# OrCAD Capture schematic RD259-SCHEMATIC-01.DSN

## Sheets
1 2: size A3
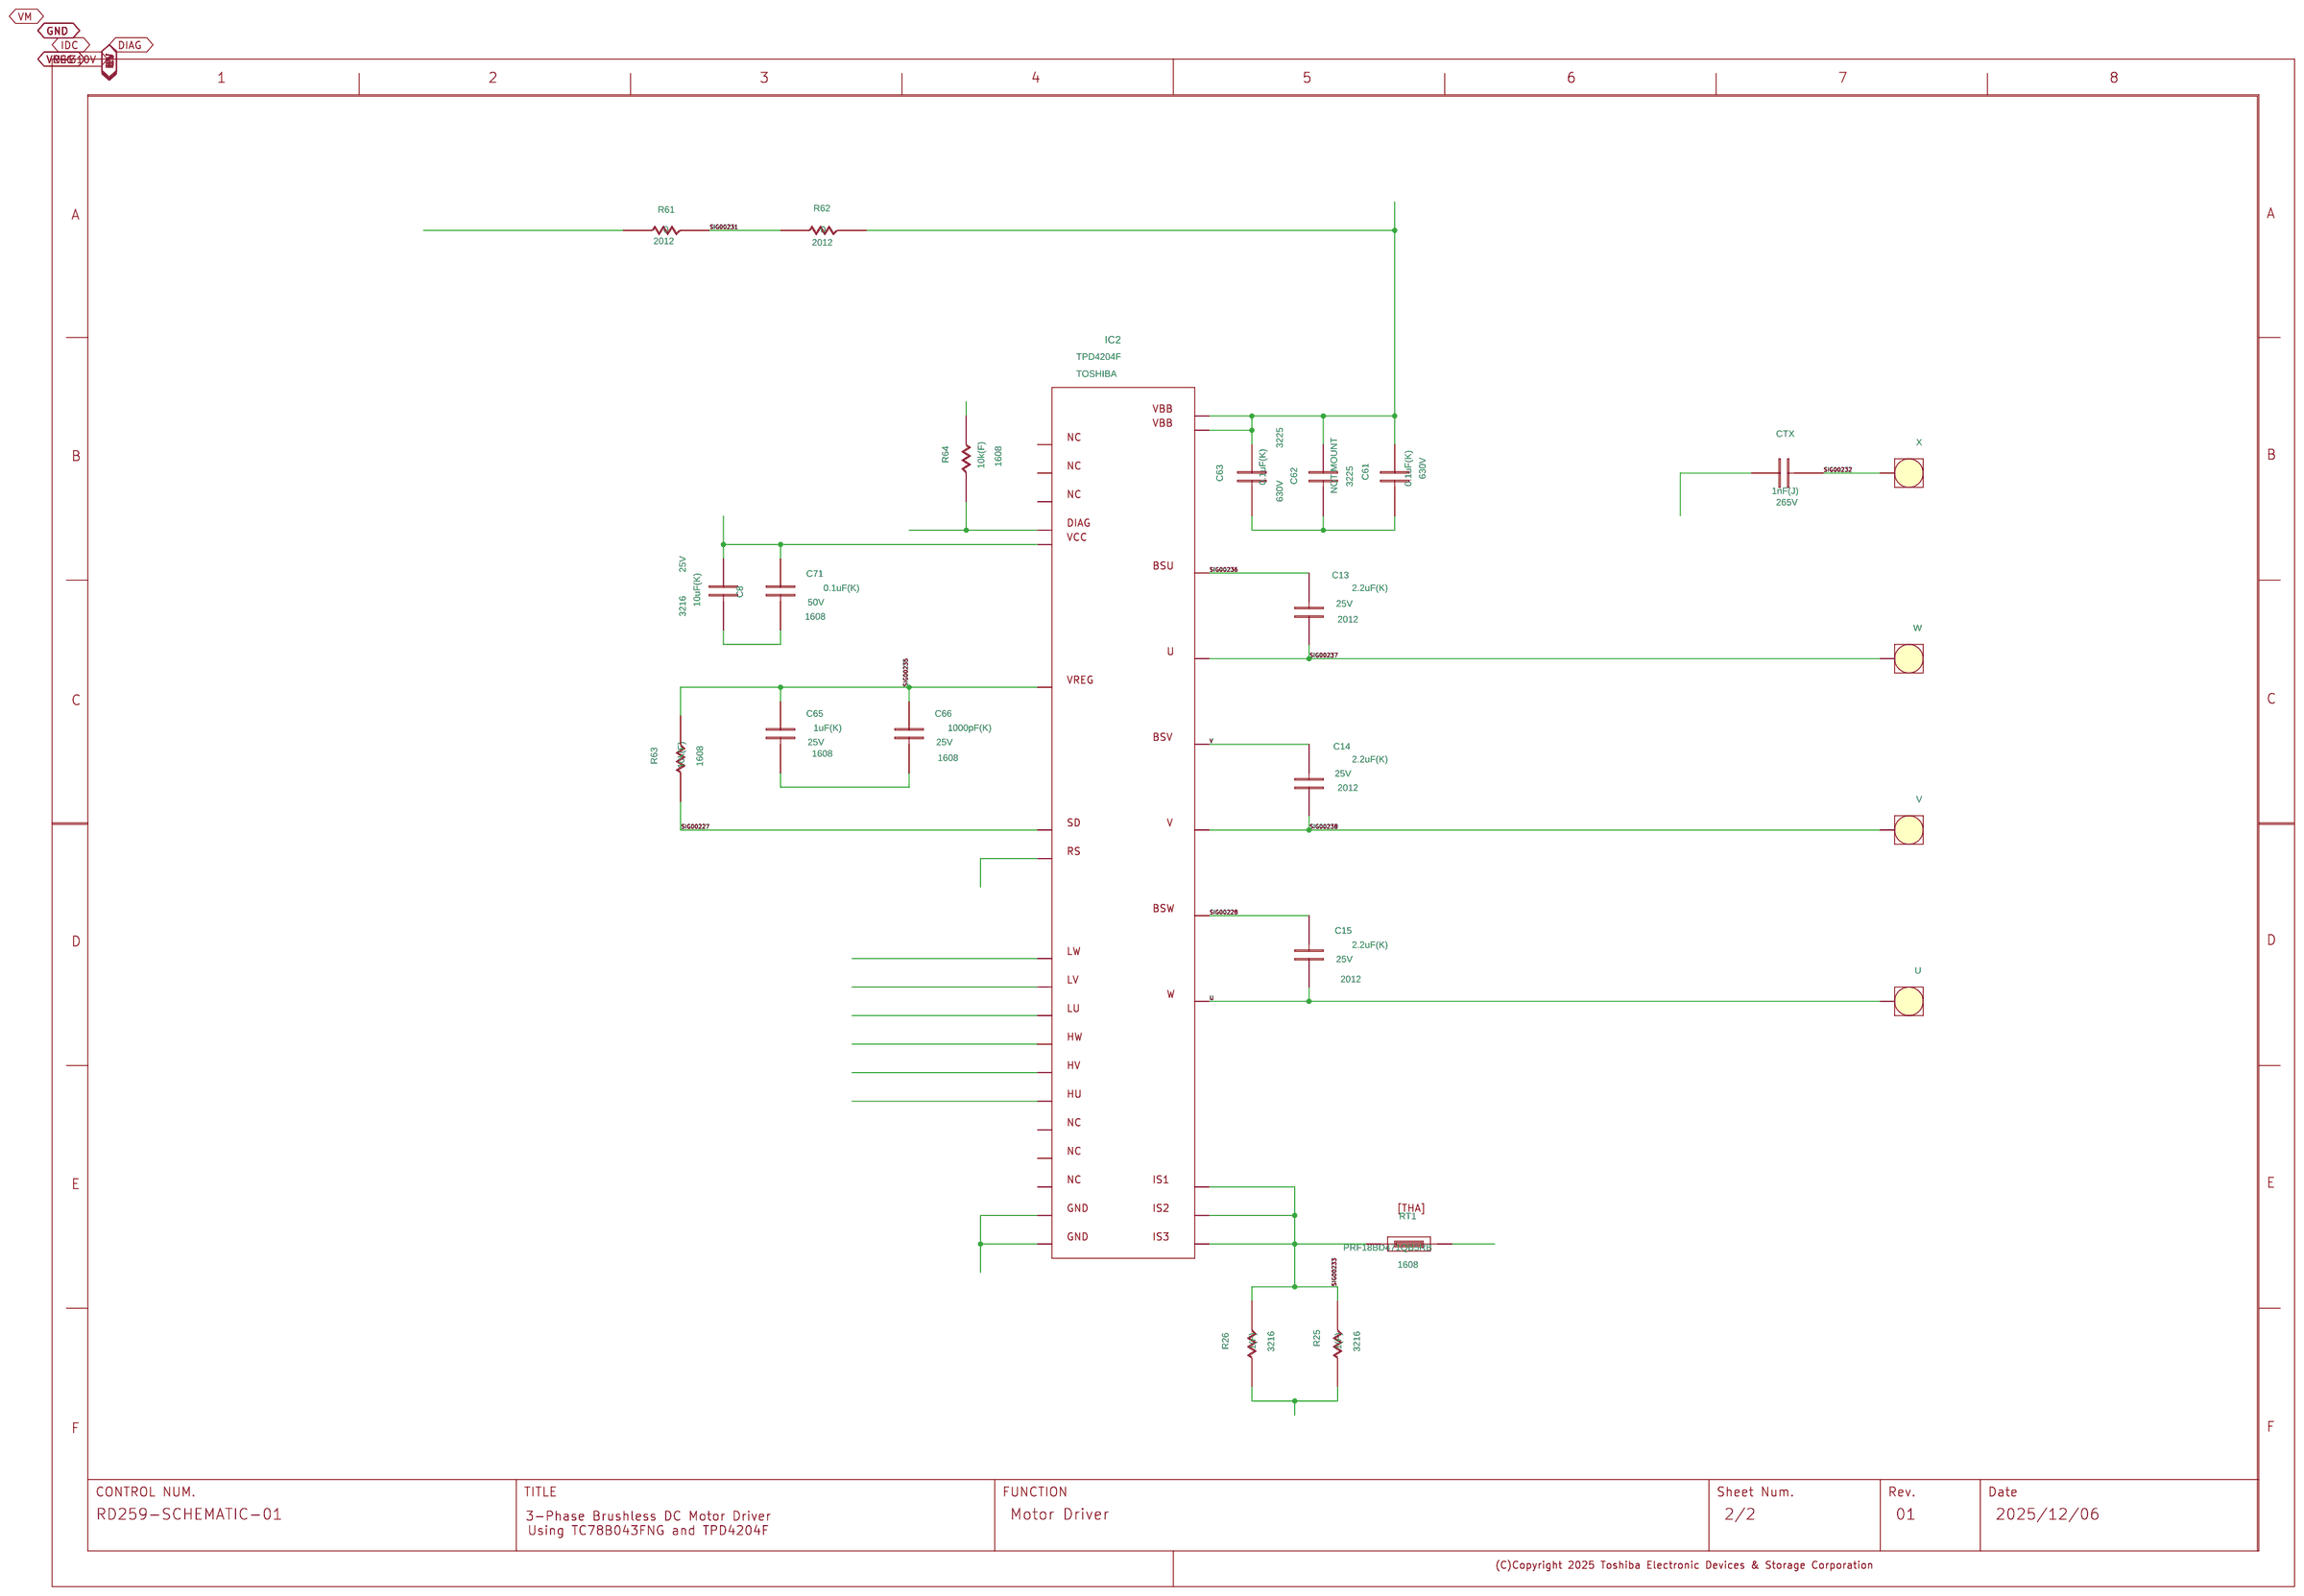
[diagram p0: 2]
2 1: size A3
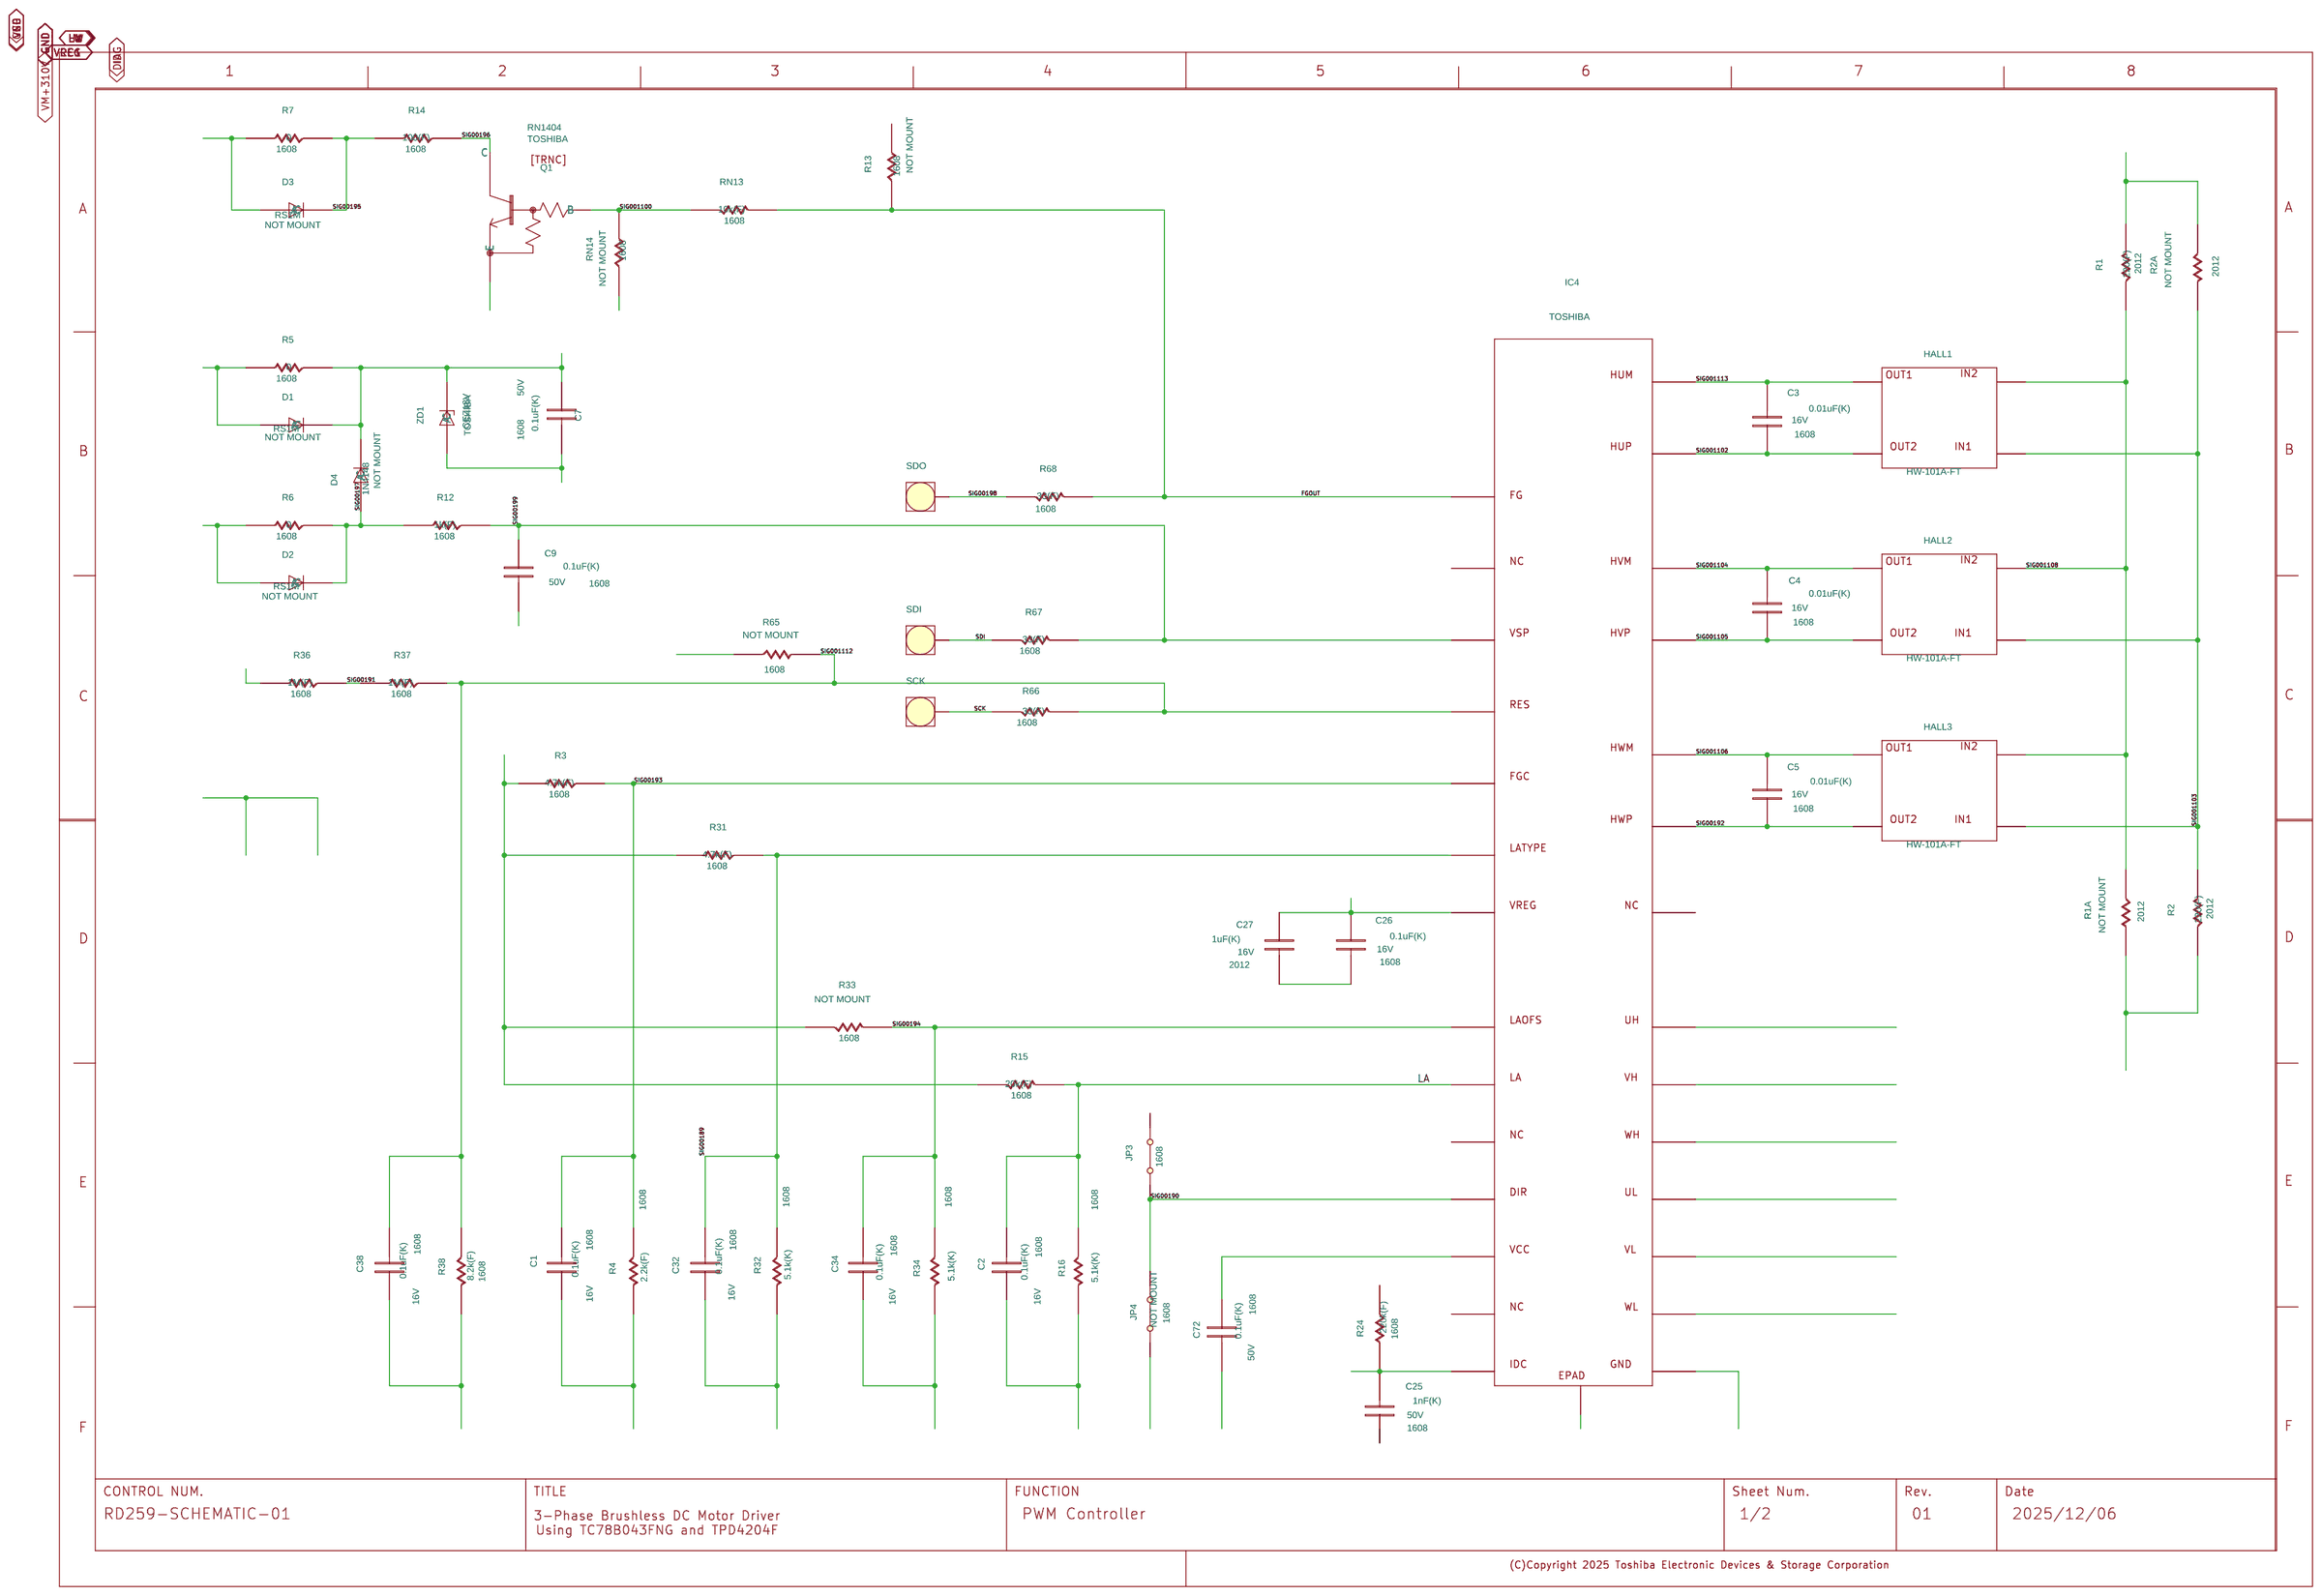
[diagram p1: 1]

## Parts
sheet 1
C1  C
C2  C
C3  C
C4  C
C5  C
C7  C
C9  C
C25  C
C26  C
C27  C
C32  C
C34  C
C38  C
C72  C
D1  D
D2  D
D3  D
D4  D
HALL1  HW-101A-FT
HALL2  HW-101A-FT
HALL3  HW-101A-FT
IC4  TC78B043FNG
JP3  JP
JP4  JP
Q1  TRNC
R1  R
R1A  R
R2  R
R2A  R
R3  R
R4  R
R5  R
R6  R
R7  R
R12  R
R13  R
R14  R
R15  R
R16  R
R24  R
R31  R
R32  R
R33  R
R34  R
R36  R
R37  R
R38  R
R65  R
R66  R
R67  R
R68  R
RN13  R
RN14  R
SCK  PAD_FOR_BLDCS50
SDI  PAD_FOR_BLDCS50
SDO  PAD_FOR_BLDCS50
U?#1  WAKU_DEF100
ZD1  ZD
sheet 2
C8  C
C13  C
C14  C
C15  C
C61  C
C62  C
C63  C
C65  C
C66  C
C71  C
CTX  C
IC2  TPD4204F
R25  R
R26  R
R61  R
R62  R
R63  R
R64  R
RT1  THA
U  PAD_FOR_BLDCS50
U?#2  WAKU_DEF100
V  PAD_FOR_BLDCS50
W  PAD_FOR_BLDCS50
X  PAD_FOR_BLDCS50

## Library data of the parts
C1 C2 C26 C32 C34 C38 = C: COMPONENTTYPE: 4; SAVECOUNT: 0; SIZECODESMD: 1608; VAL1: 0.1uF(K); VAL2: 16V
C3-C5 = C: COMPONENTTYPE: 4; SAVECOUNT: 0; SIZECODESMD: 1608; VAL1: 0.01uF(K); VAL2: 16V
C7 C9 C71 C72 = C: COMPONENTTYPE: 4; SAVECOUNT: 0; SIZECODESMD: 1608; VAL1: 0.1uF(K); VAL2: 50V
C25 = C: COMPONENTTYPE: 4; SAVECOUNT: 0; SIZECODESMD: 1608; VAL1: 1nF(K); VAL2: 50V
C27 = C: COMPONENTTYPE: 4; SAVECOUNT: 0; SIZECODESMD: 2012; VAL1: 1uF(K); VAL2: 16V
D1-D3 = D: COMPONENTTYPE: 4; NOTMNT: NOT MOUNT; VAL3: RS1M
D4 = D: COMPONENTTYPE: 4; NOTMNT: NOT MOUNT; VAL3: 1N4148
HALL1-HALL3 = HW-101A-FT: COMPONENTTYPE: 4
IC4 = TC78B043FNG: COMPONENTTYPE: 4; USERCOMPTEXT3: TOSHIBA
JP3 = JP: COMPONENTTYPE: 4; SAVECOUNT: 0; SIZECODESMD: 1608
JP4 = JP: COMPONENTTYPE: 4; NOTMNT: NOT MOUNT; SAVECOUNT: 0; SIZECODESMD: 1608
Q1 = TRNC: COMPONENTTYPE: 4; DEVICE: RN1404; SAVECOUNT: 0; USERCOMPTEXT3: TOSHIBA; VAL3: RN1404
R1 R2 = R: COMPONENTTYPE: 4; SAVECOUNT: 0; SIZECODESMD: 2012; VAL1: 220(F); VAL2: 100mW
R1A R2A = R: COMPONENTTYPE: 4; NOTMNT: NOT MOUNT; SAVECOUNT: 0; SIZECODESMD: 2012
R3 R31 = R: COMPONENTTYPE: 4; SAVECOUNT: 0; SIZECODESMD: 1608; VAL1: 4.7k(F); VAL2: 100mW
R4 = R: COMPONENTTYPE: 4; SAVECOUNT: 0; SIZECODESMD: 1608; VAL1: 2.2k(F); VAL2: 100mW
R5-R7 = R: COMPONENTTYPE: 4; SAVECOUNT: 0; SIZECODESMD: 1608; VAL1: 0
R12 = R: COMPONENTTYPE: 4; SAVECOUNT: 0; SIZECODESMD: 1608; VAL1: 1k(F); VAL2: 100mW
R13 R33 R65 RN14 = R: COMPONENTTYPE: 4; NOTMNT: NOT MOUNT; SAVECOUNT: 0; SIZECODESMD: 1608
R14 = R: COMPONENTTYPE: 4; SAVECOUNT: 0; SIZECODESMD: 1608; VAL1: 100(F); VAL2: 100mW
R15 = R: COMPONENTTYPE: 4; SAVECOUNT: 0; SIZECODESMD: 1608; VAL1: 20k(F); VAL2: 100mW
R16 R32 R34 = R: COMPONENTTYPE: 4; SAVECOUNT: 0; SIZECODESMD: 1608; VAL1: 5.1k(K); VAL2: 100mW
R24 = R: COMPONENTTYPE: 4; SAVECOUNT: 0; SIZECODESMD: 1608; VAL1: 220k(F); VAL2: 100mW
R36 R37 = R: COMPONENTTYPE: 4; SAVECOUNT: 0; SIZECODESMD: 1608; VAL1: 1M(F); VAL2: 100mW
R38 = R: COMPONENTTYPE: 4; SAVECOUNT: 0; SIZECODESMD: 1608; VAL1: 8.2k(F); VAL2: 100mW
R66-R68 = R: COMPONENTTYPE: 4; SAVECOUNT: 0; SIZECODESMD: 1608; VAL1: 33(F); VAL2: 100mW
R63 R64 RN13 = R: COMPONENTTYPE: 4; SAVECOUNT: 0; SIZECODESMD: 1608; VAL1: 10k(F); VAL2: 100mW
SCK SDI SDO U V W X = PAD_FOR_BLDCS50: COMPONENTTYPE: 4; DEVICE: PAD
U?#1 = WAKU_DEF100: COMPONENTTYPE: 2; DATE: 2025/12/06; DRAWINGNUMBER: RD259-SCHEMATIC-01; FUNCTION: PWM Controller; REVISION: 01; SAVECOUNT: 3; SHEETNUMBER: 1/2; SHTSAVECOUNT: 4; TITLE: 3-Phase Brushless DC Motor Driver / Using TC78B043FNG and TPD4204F; UPDATEDATE: 2025.12.8; UPDATETIME: 15:25:21
ZD1 = ZD: COMPONENTTYPE: 4; USERCOMPTEXT3: TOSHIBA; VAL3: CEZ18V
C8 = C: COMPONENTTYPE: 4; SAVECOUNT: 0; SIZECODESMD: 3216; VAL1: 10uF(K); VAL2: 25V
C13-C15 = C: COMPONENTTYPE: 4; NOTMNT: MOUNT; SAVECOUNT: 0; SIZECODESMD: 2012; USEWITHLAYOUT: YES; VAL1: 2.2uF(K); VAL2: 25V
C61 = C: COMPONENTTYPE: 4; SAVECOUNT: 0; VAL1: 0.1uF(K); VAL2: 630V
C62 = C: COMPONENTTYPE: 4; NOTMNT: NOT MOUNT; SAVECOUNT: 0; SIZECODESMD: 3225
C63 = C: COMPONENTTYPE: 4; SAVECOUNT: 0; SIZECODESMD: 3225; USEWITHLAYOUT: YES; VAL1: 0.1uF(K); VAL2: 630V
C65 = C: COMPONENTTYPE: 4; SAVECOUNT: 0; SIZECODESMD: 1608; VAL1: 1uF(K); VAL2: 25V
C66 = C: COMPONENTTYPE: 4; SAVECOUNT: 0; SIZECODESMD: 1608; VAL1: 1000pF(K); VAL2: 25V
CTX = C: COMPONENTTYPE: 4; SAVECOUNT: 0; VAL1: 1nF(J); VAL2: 265V
IC2 = TPD4204F: COMPONENTTYPE: 4; USERCOMPTEXT3: TOSHIBA
R25 R26 = R: COMPONENTTYPE: 4; SAVECOUNT: 0; SIZECODESMD: 3216; VAL1: 1(F); VAL2: 500mW
R61 R62 = R: COMPONENTTYPE: 4; SAVECOUNT: 0; SIZECODESMD: 2012; VAL1: 0
RT1 = THA: COMPONENTTYPE: 4; DEVICE: PRF18BD471QB5RB; SIZECODESMD: 1608; VAL3: PRF18BD471QB5RB
U?#2 = WAKU_DEF100: COMPONENTTYPE: 2; DATE: 2025/12/06; DRAWINGNUMBER: RD259-SCHEMATIC-01; FUNCTION: Motor Driver; REVISION: 01; SAVECOUNT: 3; SHEETNUMBER: 2/2; SHTSAVECOUNT: 3; TITLE: 3-Phase Brushless DC Motor Driver / Using TC78B043FNG and TPD4204F; UPDATEDATE: 2025.12.8; UPDATETIME: 15:25:20

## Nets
GND: C1.1 C2.1 C7.2 C8.2 C9.2 C25.1 C26.2 C27.2 C32.1 C34.1 C38.1 C61.2 C62.2 C63.2 C65.2 C66.2 C71.2 C72.2 CTX.1 IC2.8 IC2.9 IC2.16 IC4.0 IC4.15 JP4.1 Q1.3(E) R1A.1 R2.2 R4.1 R16.1 R25.1 R26.1 R32.1 R34.1 R38.1 RN14.2 ZD1.1(A)
VCC: D1.1(A) R5.1
VCC1: C7.1 C8.1 C71.1 C72.1 D1.2(C) D4.2(C) IC2.5 IC4.12 R5.2 ZD1.2(C)
DIAG: IC2.4 R64.2 R65.2
FG: D3.1(A) R7.1
FGOUT: IC4.1 R13.2 R68.1 RN13.1
HU: IC2.13 IC4.21
HV: IC2.14 IC4.20
HW: IC2.15 IC4.19
IDC: C25.2 IC4.14 R24.1 RT1.1
LA: C2.2 IC4.9 R15.1 R16.2
LU: IC2.10 IC4.18
LV: IC2.11 IC4.17
LW: IC2.12 IC4.16
SCK: R66.2 SCK.1
SDI: R67.2 SDI.1
SIG00189: C32.2 IC4.6 R31.2 R32.2
SIG00190: IC4.11 JP3.2 JP4.2
SIG00191: R36.2 R37.1
SIG00192: C5.1 HALL3.4 IC4.23
SIG00193: C1.2 IC4.5 R3.2 R4.2
SIG00194: C34.2 IC4.8 R33.1 R34.2
SIG00195: D3.2(C) R7.2 R14.1
SIG00196: Q1.2(C) R14.2
SIG00197: D2.2(C) D4.1(A) R6.2 R12.1
SIG00198: R68.2 SDO.1
SIG00199: C9.1 IC4.3 R12.2 R67.1
SIG00227: IC2.7 R63.1
SIG00228: C15.2 IC2.22
SIG00231: R61.2 R62.1
SIG00232: CTX.2 X.1
SIG00233: IC2.20 IC2.27 IC2.28 R25.2 R26.2 RT1.2
SIG00235: C65.1 C66.1 IC2.6 R63.2
SIG00236: C13.2 IC2.29
SIG00237: C13.1 IC2.30 W.1
SIG00238: C14.1 IC2.26 V.1
SIG001100: Q1.1(B) RN13.2 RN14.1
SIG001102: C3.1 HALL1.4 IC4.27
SIG001103: HALL1.1 HALL2.1 HALL3.1 R2.1 R2A.1
SIG001104: C4.2 HALL2.2 IC4.26
SIG001105: C4.1 HALL2.4 IC4.25
SIG001106: C5.2 HALL3.2 IC4.24
SIG001108: HALL1.3 HALL2.3 HALL3.3 R1.2 R1A.2
SIG001112: C38.2 IC4.4 R37.2 R38.2 R65.1 R66.1
SIG001113: C3.2 HALL1.2 IC4.28
U: C15.1 IC2.21 U.1
V: C14.2 IC2.25
VM: R61.1
VM+310V: C61.1 C62.1 C63.1 IC2.23 IC2.24 R36.1 R62.2
VREG: C26.1 C27.1 IC4.7 JP3.1 R1.1 R2A.2 R3.1 R13.1 R15.2 R24.2 R31.1 R33.2 R64.1
VSP: D2.1(A) R6.1

Not connected (* = marked no-connect by the designer): IC2 1 2 3 17 18 19; IC4 2 10 13 22
